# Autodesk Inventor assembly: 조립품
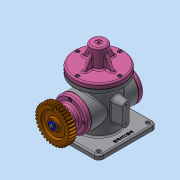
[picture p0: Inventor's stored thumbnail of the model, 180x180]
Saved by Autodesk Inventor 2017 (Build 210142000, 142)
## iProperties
Part Number: 조립품
Material: 일반
Document SubType Name: Assembly
Designer: 00-00
Author: 00-00
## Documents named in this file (21)
- C:\Users\00-00\Desktop\601206V1007\조립품.iam
- C:\Users\00-00\Desktop\601206V1007\E-링.ipt
- C:\Users\00-00\Desktop\601206V1007\가변스프링.ipt
- C:\Users\00-00\Desktop\601206V1007\개스킷 A.ipt
- C:\Users\00-00\Desktop\601206V1007\개스킷 B.ipt
- C:\Users\00-00\Desktop\601206V1007\덮개.ipt
- C:\Users\00-00\Desktop\601206V1007\뒤커버.ipt
- C:\Users\00-00\Desktop\601206V1007\링크.ipt
- C:\Users\00-00\Desktop\601206V1007\베어링 17 x 40 x 12.ipt
- C:\Users\00-00\Desktop\601206V1007\본체.ipt
- C:\Users\00-00\Desktop\601206V1007\볼트 M4 x 10.ipt
- C:\Users\00-00\Desktop\601206V1007\스퍼기어.ipt
- C:\Users\00-00\Desktop\601206V1007\슬라이더.ipt
- C:\Users\00-00\Desktop\601206V1007\앞커버.ipt
- C:\Users\00-00\Desktop\601206V1007\오일 실 17 30 8.ipt
- C:\Users\00-00\Desktop\601206V1007\와셔 4x16.ipt
- C:\Users\00-00\Desktop\601206V1007\육각 소켓 머리 볼트 M4 x 10.ipt
- C:\Users\00-00\Desktop\601206V1007\클레비스 핀 6 x 22.ipt
- 클레비스 핀 6 x 22.ipt
- C:\Users\00-00\Desktop\601206V1007\키 4 x 4 x 18.ipt
- C:\Users\00-00\Desktop\601206V1007\편심축.ipt
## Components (5 placed, 4 different names)
1. E-링:1
2. 가변스프링:1
3. 개스킷 A:1
4. 개스킷 B:1
5. 개스킷 A:2
